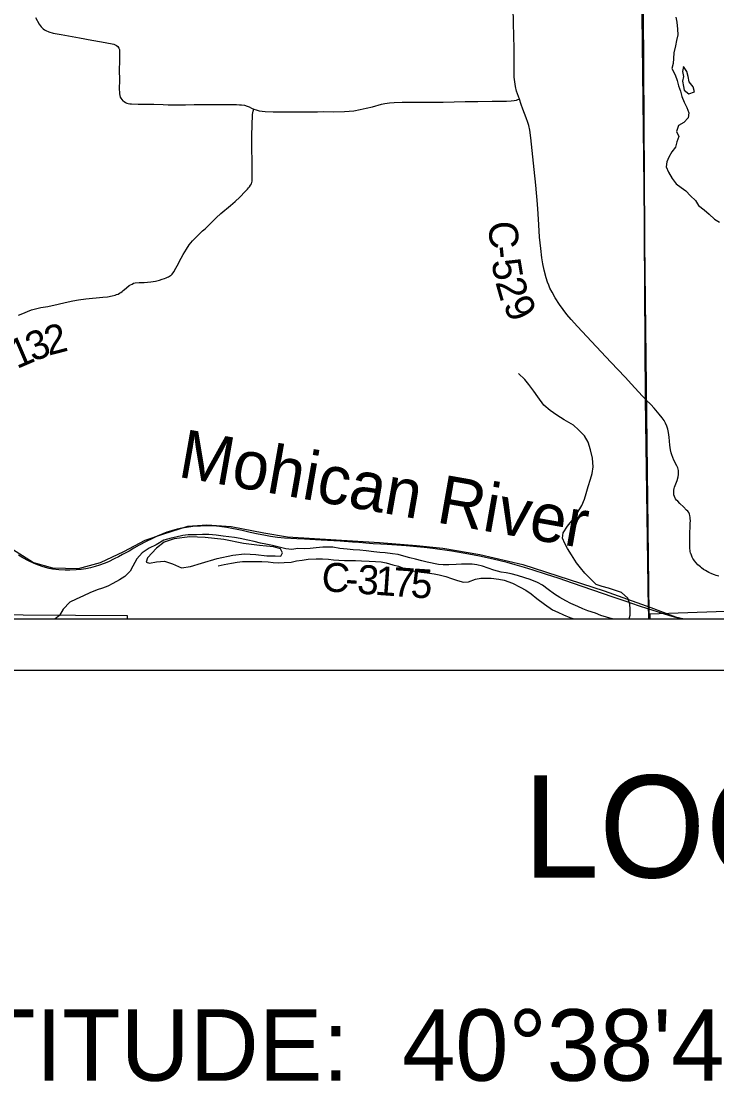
# Model space of a CAD drawing. Extents: x -7.5 to 53.5, y 0 to 22.
# Drawn here: x 3.386 to 4.748, y 13.194 to 15.27 of the extents above; entities that cross this region are included whole.
import ezdxf

# ---------------------------------------------------------------- set-up
doc = ezdxf.new("R2010")
doc.units = 0
for name, color, linetype in [('GM_X_Corporation', 7, 'Continuous'), ('GM_X_County_Road', 7, 'Continuous'), ('GM_X_County_Road_Text', 7, 'Continuous'), ('GM_X_Major_River', 7, 'Continuous'), ('GM_X_Major_River_Text', 7, 'Continuous'), ('GM_X_Minor_Lake', 7, 'Continuous'), ('GM_X_Minor_River', 7, 'Continuous'), ('GM_X_Rail_Line', 7, 'Continuous'), ('GM_X_Township_Road', 7, 'Continuous'), ('GM_X_Township_Road_Text', 7, 'Continuous'), ('SH_Data', 7, 'Continuous'), ('SH_Text', 7, 'Continuous')]:
    doc.layers.add(name, color=color, linetype=linetype)

msp = doc.modelspace()

# ---------------------------------------------------------------- linework, layer by layer
at = {"layer": 'GM_X_Corporation'}
for points in [[(2.1, 20.9), (2.1, 14.1), (4.6151, 14.1), (4.6149, 14.11), (4.6147, 14.1199), (4.6087, 14.5302), (4.6021, 15.6139)], [(4.6021, 15.6139), (4.6087, 14.5302), (4.6147, 14.1199), (4.6149, 14.11), (4.6151, 14.1), (8.9, 14.1), (8.9, 19.1887)]]:
    msp.add_lwpolyline(points, dxfattribs=at)
for points in [[(4.6172, 14.1), (5.6196, 14.1), (5.619, 14.1446), (4.6171, 14.1096)], [(2.573, 14.1), (3.5941, 14.1), (3.594, 14.1064), (2.573, 14.1127)]]:
    msp.add_lwpolyline(points, close=True, dxfattribs=at)
at = {"layer": 'GM_X_County_Road'}
for points in [[(4.3617, 15.1179), (4.356, 15.1334), (4.3539, 15.1425), (4.3524, 15.1517), (4.3516, 15.161), (4.3512, 15.1766), (4.3511, 15.2169), (4.3502, 15.2665), (4.3475, 15.3906), (4.3465, 15.462), (4.3463, 15.4961), (4.346, 15.5209), (4.345, 15.5673), (4.3444, 15.5952), (4.344, 15.6154)], [(4.6089, 14.5297), (4.6077, 14.531), (4.6066, 14.5321), (4.6023, 14.5368), (4.5812, 14.5596), (4.5685, 14.5731), (4.5409, 14.6025), (4.5219, 14.6229), (4.5028, 14.6432), (4.4752, 14.6727), (4.4627, 14.6864), (4.4547, 14.6958), (4.4472, 14.7056), (4.4402, 14.7159), (4.4319, 14.7289), (4.4258, 14.7396), (4.4215, 14.7478), (4.419, 14.7535), (4.4168, 14.7592), (4.414, 14.768), (4.4101, 14.7829), (4.4075, 14.795), (4.4055, 14.8072), (4.4033, 14.8256), (4.4013, 14.8472), (4.3997, 14.8718), (4.3983, 14.8934), (4.3969, 14.912), (4.3935, 14.949), (4.3907, 14.9799), (4.3869, 15.017), (4.3841, 15.0417), (4.3818, 15.057), (4.3799, 15.0662), (4.3783, 15.0722), (4.3752, 15.0811), (4.3685, 15.0984), (4.3654, 15.1069), (4.3617, 15.1179)], [(4.7522, 14.1837), (4.747, 14.1852), (4.7435, 14.1864), (4.7386, 14.1883), (4.7327, 14.1908), (4.7262, 14.1946), (4.7221, 14.1971), (4.7185, 14.1999), (4.7162, 14.2018), (4.7113, 14.206), (4.7075, 14.2099), (4.7044, 14.2135), (4.7031, 14.2155), (4.7016, 14.2182), (4.7002, 14.2209), (4.6992, 14.2231), (4.6977, 14.2266), (4.6972, 14.2278), (4.6968, 14.2297), (4.6962, 14.2324), (4.6955, 14.2397), (4.6952, 14.2453), (4.6952, 14.2508), (4.6951, 14.2572), (4.6955, 14.2698), (4.696, 14.2794), (4.6963, 14.2867), (4.6964, 14.293), (4.6963, 14.296), (4.6962, 14.2989), (4.6956, 14.3023), (4.6947, 14.3054), (4.6932, 14.3086), (4.6915, 14.3108), (4.6892, 14.3133), (4.6833, 14.3195), (4.6755, 14.3258), (4.6716, 14.3304), (4.6695, 14.3329), (4.6676, 14.3355), (4.6656, 14.3395), (4.6644, 14.3433), (4.6639, 14.3465), (4.6639, 14.3495), (4.6642, 14.3524), (4.6645, 14.3552), (4.6654, 14.3583), (4.6677, 14.3643), (4.6703, 14.3713), (4.6724, 14.3782), (4.6732, 14.3829), (4.6734, 14.3861), (4.6734, 14.3884), (4.6733, 14.3907), (4.6726, 14.3933), (4.6716, 14.3959), (4.67, 14.3995), (4.6644, 14.4108), (4.662, 14.4164), (4.6602, 14.4215), (4.6589, 14.4252), (4.6575, 14.4313), (4.6562, 14.4405), (4.655, 14.456), (4.6538, 14.4653), (4.6524, 14.4714), (4.6505, 14.4774), (4.648, 14.4832), (4.645, 14.4887), (4.6414, 14.4939), (4.6356, 14.5012), (4.6253, 14.5129), (4.6189, 14.5197), (4.6089, 14.5297)], [(4.615, 14.1193), (4.5947, 14.126), (4.5836, 14.1297), (4.5728, 14.1333), (4.5452, 14.1426), (4.4658, 14.1701), (4.4394, 14.179), (4.4126, 14.1876), (4.3888, 14.1955), (4.3713, 14.2009), (4.3531, 14.2062), (4.3379, 14.2103), (4.3102, 14.217), (4.2837, 14.2228), (4.2627, 14.2271), (4.229, 14.2327), (4.1922, 14.2379), (4.1754, 14.2398), (4.1397, 14.2432), (4.1026, 14.2456), (4.0904, 14.2463), (4.0755, 14.2474), (4.0612, 14.2485), (4.0472, 14.2496), (4.0351, 14.2505), (4.0106, 14.2521), (3.9735, 14.2543), (3.9515, 14.2556), (3.9406, 14.2561), (3.9257, 14.2568), (3.9018, 14.2584), (3.8877, 14.2596), (3.8741, 14.2614), (3.8612, 14.2638), (3.8499, 14.2661), (3.8345, 14.2695), (3.8188, 14.2729), (3.789, 14.279), (3.7744, 14.2811), (3.7622, 14.2822), (3.7498, 14.2824), (3.7369, 14.282), (3.722, 14.2811), (3.7097, 14.2794), (3.7006, 14.2778), (3.6916, 14.2758), (3.6802, 14.2728), (3.6712, 14.2699), (3.6631, 14.2666), (3.652, 14.2619), (3.6415, 14.257), (3.6309, 14.2516), (3.617, 14.2443), (3.6067, 14.2383), (3.5973, 14.233), (3.5841, 14.2259), (3.5765, 14.2218), (3.5683, 14.2175), (3.557, 14.2121), (3.5484, 14.2084), (3.5396, 14.2052), (3.5307, 14.2024), (3.5216, 14.2001), (3.5124, 14.1983), (3.5031, 14.1969), (3.4938, 14.196), (3.4813, 14.1955), (3.472, 14.1956), (3.4595, 14.1964), (3.4471, 14.1978), (3.4409, 14.1989), (3.4288, 14.2021), (3.42, 14.2051), (3.4112, 14.2086), (3.4001, 14.2136), (3.3889, 14.2198), (3.381, 14.2248)], [(4.6457, 14.1095), (4.6301, 14.1146), (4.615, 14.1193)], [(4.6775, 14.1), (4.661, 14.1047), (4.6457, 14.1095)]]:
    msp.add_lwpolyline(points, dxfattribs=at)
at = {"layer": 'GM_X_Major_River'}
for points in [[(3.83, 14.254), (3.8148, 14.2577), (3.8037, 14.2598), (3.7927, 14.2609), (3.7817, 14.2623), (3.7677, 14.2641), (3.7533, 14.2651), (3.7407, 14.2653), (3.729, 14.2648), (3.7132, 14.2645), (3.7028, 14.2631), (3.6889, 14.2604), (3.6797, 14.2581), (3.665, 14.2543), (3.65, 14.2454), (3.6367, 14.2389), (3.6231, 14.2297), (3.6126, 14.2179), (3.6044, 14.2037), (3.5996, 14.1938), (3.5887, 14.1831), (3.5788, 14.1769), (3.5653, 14.1692), (3.5554, 14.1642), (3.5449, 14.1603), (3.535, 14.1568), (3.5207, 14.1514), (3.5082, 14.1452), (3.4939, 14.139), (3.481, 14.1328), (3.4683, 14.1194), (3.4608, 14.1068), (3.4522, 14.1)], [(3.6331, 14.2199), (3.6305, 14.2112), (3.637, 14.209), (3.651, 14.2118), (3.6665, 14.213), (3.6821, 14.2079), (3.7, 14.2001), (3.7178, 14.2025), (3.739, 14.2092), (3.77, 14.2185), (3.8003, 14.2249), (3.8234, 14.2274), (3.8454, 14.2261), (3.867, 14.2236), (3.8833, 14.2234), (3.8943, 14.2231), (3.898, 14.2296), (3.8938, 14.2375), (3.8801, 14.2412), (3.8528, 14.244), (3.8213, 14.2475), (3.7825, 14.2555), (3.7465, 14.2593), (3.7165, 14.2609), (3.6858, 14.2572), (3.6662, 14.2506), (3.6511, 14.2383)], [(4.5439, 14.1), (4.5435, 14.1001), (4.5325, 14.1034), (4.5214, 14.1071), (4.5108, 14.1112), (4.4959, 14.116), (4.4857, 14.12), (4.4758, 14.1241), (4.4624, 14.1305), (4.4525, 14.1353), (4.4407, 14.142), (4.4301, 14.1484), (4.4182, 14.1577), (4.4071, 14.166), (4.3969, 14.1712), (4.3828, 14.1771), (4.3725, 14.1808), (4.3581, 14.1849), (4.3455, 14.1886), (4.3356, 14.1904), (4.3261, 14.1918), (4.3113, 14.1955), (4.3007, 14.1992), (4.2893, 14.2032), (4.2786, 14.2062), (4.2691, 14.2076), (4.2483, 14.2074), (4.238, 14.2069), (4.2232, 14.206), (4.2126, 14.2059), (4.2031, 14.2066), (4.1811, 14.211), (4.1705, 14.2139), (4.1583, 14.2168), (4.1473, 14.2197), (4.1351, 14.2231), (4.1241, 14.226), (4.1131, 14.2278), (4.099, 14.2292), (4.0884, 14.2302), (4.0763, 14.2312), (4.0615, 14.2334), (4.0489, 14.2344), (4.0364, 14.2354), (4.0246, 14.2365), (4.0102, 14.2382), (3.9965, 14.2404), (3.9863, 14.2406), (3.9764, 14.2406), (3.9636, 14.2393), (3.9518, 14.2377), (3.9412, 14.2372), (3.9279, 14.2378), (3.9158, 14.2362), (3.9044, 14.2376), (3.8911, 14.2405), (3.8778, 14.2438), (3.8653, 14.2467), (3.8543, 14.2485), (3.8421, 14.2515), (3.83, 14.254)], [(3.6511, 14.2383), (3.6331, 14.2199)], [(3.7716, 14.2041), (3.7837, 14.2065), (3.7981, 14.2093), (3.8091, 14.2109), (3.8193, 14.2122), (3.8303, 14.2127), (3.8406, 14.2127), (3.8572, 14.2125), (3.8694, 14.2119), (3.8793, 14.2108), (3.8899, 14.2102), (3.9009, 14.2106), (3.9149, 14.2115), (3.9251, 14.2135), (3.9361, 14.2151), (3.9478, 14.2168), (3.9638, 14.2177), (3.9763, 14.2178), (3.9877, 14.2168), (3.9975, 14.2161), (4.0078, 14.215), (4.0188, 14.2144), (4.0302, 14.2145), (4.0404, 14.2142), (4.0525, 14.2139), (4.0677, 14.2133), (4.0795, 14.2127), (4.0912, 14.2116), (4.1007, 14.2102), (4.1137, 14.2062), (4.1251, 14.2032), (4.1346, 14.1995), (4.1441, 14.1962), (4.1581, 14.1933), (4.1695, 14.1919), (4.1809, 14.1905), (4.195, 14.1883), (4.2045, 14.1865), (4.2174, 14.1832), (4.2288, 14.1795), (4.2406, 14.1755), (4.252, 14.1721), (4.2618, 14.173), (4.2754, 14.1777), (4.2864, 14.1797), (4.2967, 14.1801), (4.3065, 14.1802), (4.3213, 14.1781), (4.332, 14.1759), (4.3483, 14.17), (4.3632, 14.1625), (4.3742, 14.1562), (4.3845, 14.1491), (4.396, 14.1401), (4.4105, 14.1288), (4.4265, 14.118), (4.4368, 14.1131), (4.4482, 14.1079), (4.4604, 14.1031), (4.468, 14.1)]]:
    msp.add_lwpolyline(points, dxfattribs=at)
at = {"layer": 'GM_X_Minor_Lake'}
for points in [[(4.7019, 15.1418), (4.6942, 15.1516), (4.6922, 15.1618), (4.6895, 15.1717), (4.6833, 15.1819), (4.6808, 15.172), (4.6828, 15.1621), (4.6813, 15.1526), (4.6833, 15.1424), (4.6841, 15.1356)], [(4.6841, 15.1356), (4.6933, 15.1284), (4.7043, 15.132), (4.7019, 15.1418)]]:
    msp.add_lwpolyline(points, dxfattribs=at)
at = {"layer": 'GM_X_Minor_River'}
for points in [[(4.6681, 15.2785), (4.6697, 15.2682), (4.6713, 15.255), (4.6718, 15.2436), (4.6692, 15.2322), (4.6674, 15.2219), (4.6642, 15.2086), (4.6635, 15.1976), (4.6628, 15.1874), (4.6603, 15.1779), (4.6664, 15.165), (4.6703, 15.154), (4.6731, 15.1438), (4.677, 15.1332), (4.6797, 15.1226), (4.684, 15.1117), (4.6898, 15.1015), (4.6933, 15.0909), (4.6922, 15.0814), (4.6836, 15.0718), (4.673, 15.0661), (4.6693, 15.0546), (4.674, 15.0448), (4.6699, 15.0342), (4.6673, 15.0239), (4.6602, 15.0144), (4.6546, 15.0044), (4.6506, 14.9949), (4.6488, 14.985), (4.6534, 14.9748), (4.6611, 14.9624), (4.6688, 14.9522), (4.6783, 14.9447), (4.6878, 14.9383), (4.6966, 14.9282), (4.7062, 14.9191), (4.7127, 14.9093), (4.7234, 14.9007), (4.7333, 14.8928), (4.7437, 14.883), (4.7536, 14.8767)], [(4.5764, 14.1), (4.5783, 14.1072), (4.5786, 14.1194), (4.5777, 14.1292), (4.5742, 14.1406), (4.5616, 14.1515), (4.5479, 14.1567), (4.5361, 14.1603), (4.5236, 14.1636), (4.5122, 14.1677), (4.5003, 14.1794), (4.49, 14.1899), (4.4815, 14.2004), (4.4735, 14.2102), (4.4639, 14.2253), (4.4558, 14.2378), (4.4504, 14.248), (4.4461, 14.2582), (4.4472, 14.2684), (4.4558, 14.2814), (4.467, 14.2952), (4.4745, 14.3074), (4.4842, 14.3219), (4.4894, 14.3345), (4.4924, 14.3455), (4.4964, 14.3592), (4.5012, 14.374), (4.5042, 14.385), (4.5059, 14.3976), (4.5046, 14.415), (4.5007, 14.4313), (4.4964, 14.4461), (4.4891, 14.4585), (4.4772, 14.4706), (4.4673, 14.4796), (4.4494, 14.4896), (4.4352, 14.499), (4.4219, 14.5084), (4.4097, 14.5189), (4.3978, 14.5347), (4.3897, 14.546), (4.3801, 14.5588), (4.3724, 14.5686), (4.3598, 14.5806)]]:
    msp.add_lwpolyline(points, dxfattribs=at)
at = {"layer": 'GM_X_Rail_Line'}
for points in [[(3.3618, 14.2413), (3.41, 14.2105), (3.4474, 14.1998), (3.4983, 14.1987), (3.5415, 14.2107), (3.587, 14.2322), (3.6287, 14.2543), (3.6633, 14.2662), (3.7123, 14.2819), (3.7492, 14.284), (3.7973, 14.2809), (3.8609, 14.2684), (3.9074, 14.2607), (4.0874, 14.2498), (4.1603, 14.2436), (4.2115, 14.2389), (4.2844, 14.2265), (4.3682, 14.2066), (4.5278, 14.1548), (4.619, 14.1225)], [(4.619, 14.1225), (4.6676, 14.1045), (4.6843, 14.1)]]:
    msp.add_lwpolyline(points, dxfattribs=at)
at = {"layer": 'GM_X_Township_Road'}
for points in [[(3.4138, 15.2776), (3.4214, 15.2645), (3.4231, 15.2619), (3.4249, 15.2595), (3.427, 15.2573), (3.4292, 15.2553), (3.4317, 15.2535), (3.4345, 15.2519), (3.4402, 15.2495), (3.4489, 15.2472), (3.4645, 15.2445), (3.4786, 15.2419), (3.5, 15.2375), (3.5242, 15.233), (3.543, 15.2297), (3.564, 15.2259), (3.5672, 15.2251), (3.5701, 15.2243), (3.5729, 15.223), (3.5755, 15.2205), (3.5774, 15.2178), (3.5782, 15.215), (3.5784, 15.2117), (3.5786, 15.2054), (3.5783, 15.193), (3.5781, 15.1743), (3.5782, 15.1557), (3.578, 15.137), (3.5782, 15.1309), (3.5784, 15.1278), (3.5789, 15.1248), (3.5798, 15.1219), (3.5812, 15.1193), (3.5829, 15.1168), (3.585, 15.1146), (3.5874, 15.1128), (3.59, 15.1112), (3.5928, 15.11), (3.5957, 15.1091), (3.599, 15.1085), (3.6022, 15.1082), (3.615, 15.108), (3.646, 15.1079), (3.6643, 15.1074), (3.674, 15.1065), (3.6834, 15.1065), (3.6915, 15.1065), (3.6985, 15.1067), (3.7076, 15.1068), (3.7247, 15.107), (3.7343, 15.1072), (3.7536, 15.1074), (3.7769, 15.1072), (3.7964, 15.1071), (3.8076, 15.107), (3.8134, 15.1066), (3.8177, 15.1064), (3.8236, 15.1056), (3.8287, 15.1041), (3.8325, 15.1026), (3.8368, 15.1001), (3.8414, 15.0981)], [(3.8414, 15.0981), (3.846, 15.0965), (3.8519, 15.095), (3.8579, 15.0939), (3.864, 15.0934), (3.8795, 15.093), (3.8981, 15.093), (3.923, 15.0929), (3.9478, 15.093), (3.9665, 15.0931), (3.9789, 15.0932), (3.9984, 15.093), (4.019, 15.0936), (4.0283, 15.094), (4.0375, 15.0951), (4.0497, 15.0972), (4.0618, 15.0998), (4.0738, 15.1029), (4.0919, 15.1076), (4.098, 15.1089), (4.1072, 15.1102), (4.1166, 15.1111), (4.1321, 15.1115), (4.1506, 15.1115), (4.1661, 15.1116), (4.1968, 15.1119), (4.2122, 15.1121), (4.2339, 15.1125), (4.2556, 15.1128), (4.2805, 15.1131), (4.3085, 15.1135), (4.3364, 15.1138), (4.3457, 15.1142), (4.3516, 15.115), (4.3557, 15.1159), (4.3586, 15.1168), (4.3617, 15.1179)], [(3.3809, 14.6945), (3.3893, 14.6981), (3.3982, 14.7022), (3.4063, 14.7052), (3.4143, 14.7073), (3.4246, 14.7095), (3.4382, 14.7117), (3.4583, 14.716), (3.4721, 14.7198), (3.4872, 14.7229), (3.4982, 14.7247), (3.5124, 14.7267), (3.546, 14.7298), (3.5551, 14.7309), (3.564, 14.7325), (3.5699, 14.734), (3.5728, 14.735), (3.5756, 14.7362), (3.5784, 14.7376), (3.581, 14.7392), (3.5835, 14.741), (3.5859, 14.7429), (3.5882, 14.7449), (3.5924, 14.7485), (3.5977, 14.7526), (3.6003, 14.7543), (3.603, 14.7557), (3.6059, 14.7572), (3.6093, 14.7581), (3.6172, 14.7586), (3.6269, 14.7588), (3.64, 14.7598), (3.6489, 14.7611), (3.657, 14.7636), (3.6623, 14.7652), (3.6666, 14.7666), (3.6696, 14.7677), (3.6724, 14.7689), (3.6746, 14.7697), (3.6764, 14.7709), (3.6782, 14.7722), (3.6799, 14.7733), (3.6815, 14.7753), (3.6848, 14.7794), (3.689, 14.7867), (3.6916, 14.7916), (3.6939, 14.7961), (3.6963, 14.8008), (3.6992, 14.8063), (3.7033, 14.8136), (3.7094, 14.8239), (3.7152, 14.8324), (3.7217, 14.8401), (3.7299, 14.8486), (3.7413, 14.86), (3.746, 14.864), (3.7571, 14.8747), (3.768, 14.8855), (3.7771, 14.8937), (3.796, 14.9092), (3.8051, 14.9174), (3.8139, 14.926), (3.8246, 14.9372), (3.829, 14.9415), (3.8311, 14.9438), (3.8332, 14.9463), (3.8352, 14.949), (3.8367, 14.9516), (3.8376, 14.9544), (3.8382, 14.9574), (3.8385, 14.9636), (3.8386, 14.9729), (3.8381, 14.9978), (3.8377, 15.0195), (3.8379, 15.0412), (3.8385, 15.0723), (3.8388, 15.0816), (3.8392, 15.0878), (3.8396, 15.0909), (3.8403, 15.0941), (3.8414, 15.0981)]]:
    msp.add_lwpolyline(points, dxfattribs=at)
at = {"layer": 'SH_Data'}
for p, q in [((2.1, 14.1), (8.9, 14.1)), ((2, 14), (9, 14))]:
    msp.add_line(p, q, dxfattribs=at)
msp.add_lwpolyline([(8.9, 19.1896), (4.5566, 19.1336), (4.6149, 14.11), (4.6151, 14.1)], dxfattribs=at)

# ---------------------------------------------------------------- texts
at = {"layer": 'GM_X_County_Road_Text'}
for s, rotation, p in [('C', 273.3077, (4.301, 14.8776)), ('-', 275.7703, (4.3039, 14.8283)), ('5', 279.5333, (4.3068, 14.8011)), ('2', 286.1425, (4.3142, 14.7596)), ('9', 297.3003, (4.3283, 14.7147)), ('C', 355.9433, (3.9727, 14.1549)), ('3', 355.9455, (4.0426, 14.1499)), ('1', 355.9591, (4.0775, 14.1475)), ('7', 355.9988, (4.1125, 14.145)), ('5', 356.1539, (4.1475, 14.1425)), ('-', 355.9507, (4.0193, 14.1516))]:
    msp.add_text(s, height=0.0568, rotation=rotation, dxfattribs=at).set_placement(p)
at = {"layer": 'GM_X_Major_River_Text'}
msp.add_text('Mohican River', height=0.094711, rotation=349.9944, dxfattribs=at).set_placement((3.6907, 14.3787))
at = {"layer": 'GM_X_Township_Road_Text'}
for s, rotation, p in [('3', 22.4213, (3.4091, 14.6026)), ('2', 14.4742, (3.4395, 14.6153)), ('1', 23.2632, (3.3772, 14.5889))]:
    msp.add_text(s, height=0.0568, rotation=rotation, dxfattribs=at).set_placement(p)
at = {"layer": 'SH_Text'}
for s, height, p in [('LOCATION MAP', 0.2, (4.3691, 13.5938)), ('LATITUDE:  40°38\'40"     LONGITUDE:  82°12\'30"', 0.14, (3.071, 13.1959))]:
    msp.add_text(s, height=height, dxfattribs=at).set_placement(p)

doc.saveas('drawing.dxf')
